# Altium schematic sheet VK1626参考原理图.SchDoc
size A4
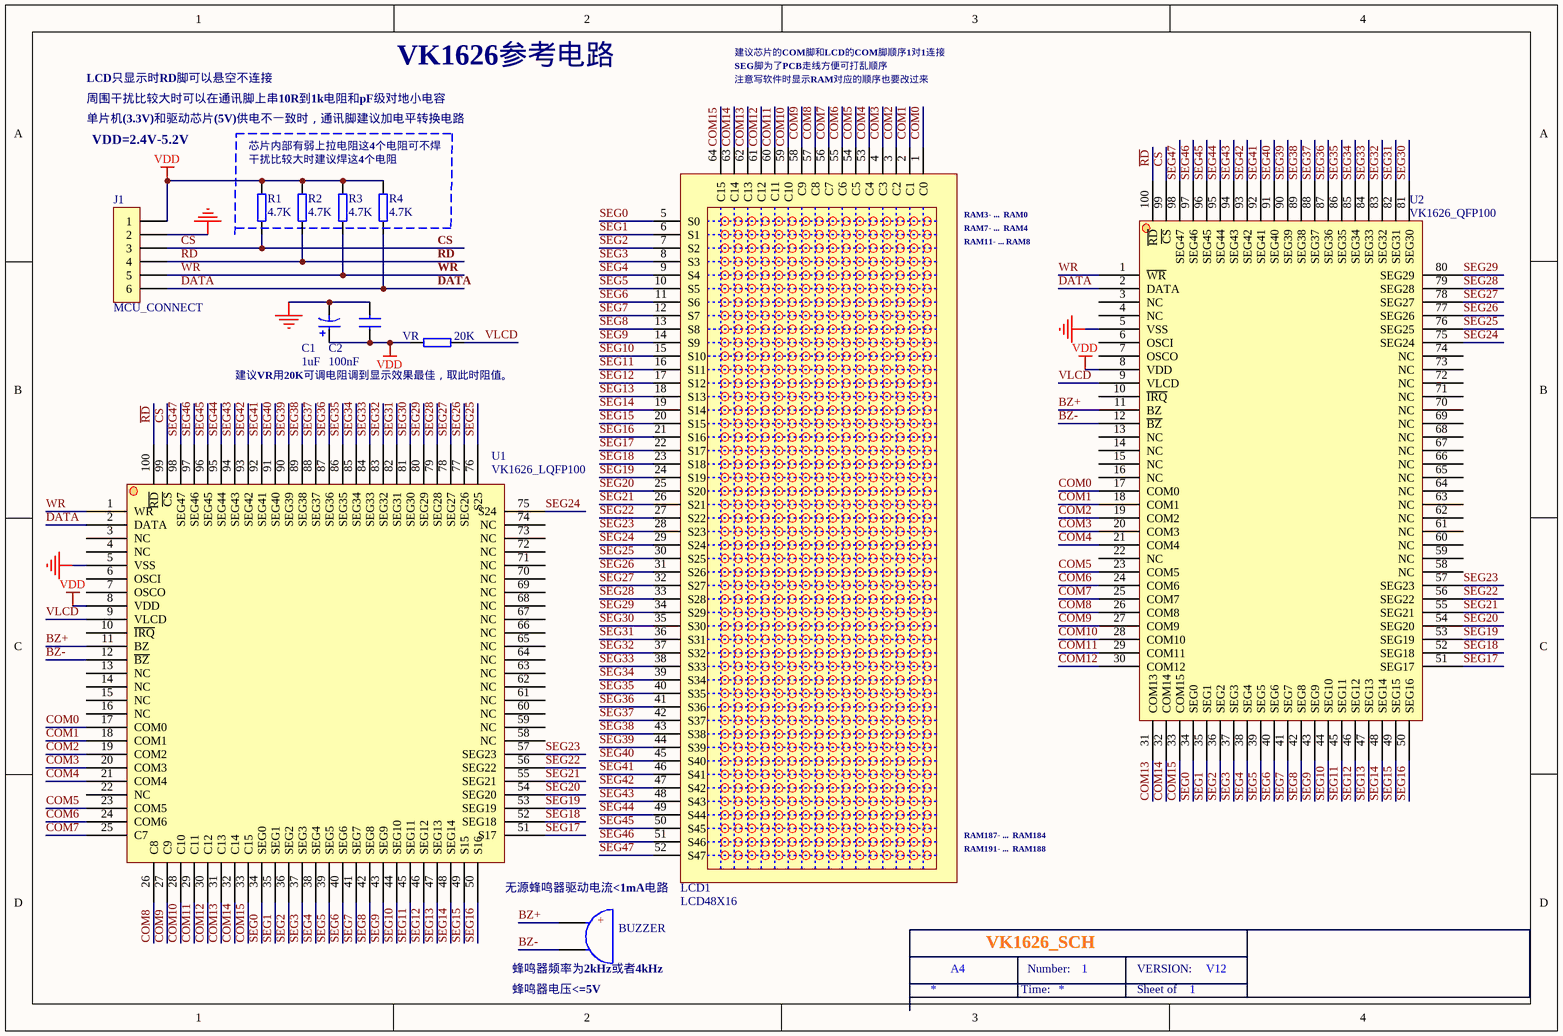
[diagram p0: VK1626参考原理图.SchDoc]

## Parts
B1  BUZZER  [BUZZER-12]
C1  1uF  [1206-C]
C2  100nF  [0603-C]
J1  MCU_CONNECT
LCD1  LCD48X16
R1  4.7K  [0603-R]
R2  4.7K  [0603-R]
R3  4.7K  [0603-R]
R4  4.7K  [0603-R]
U1  VK1626_LQFP100
U2  VK1626_QFP100
VR  20K  [0603-R]

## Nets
GND: C1.2 C2.2 J1.2 U1.5(VSS) U2.5(VSS)
VDD: C1.1 C2.1 J1.1 R1.1 R2.1 R3.1 R4.1 U1.8(VDD) U2.8(VDD) VR.1
~{CS}: U1.99(~{CS}) U2.99(~{CS})
~{RD}: U1.100(~{RD}) U2.100(~{RD})
BZ+: B1.1 U1.11(BZ) U2.11(BZ)
BZ-: B1.2 U1.12(~{BZ}) U2.12(~{BZ})
COM0: LCD1.1(C0) U1.17(COM0) U2.17(COM0)
COM1: LCD1.2(C1) U1.18(COM1) U2.18(COM1)
COM2: LCD1.3(C2) U1.19(COM2) U2.19(COM2)
COM3: LCD1.4(C3) U1.20(COM3) U2.20(COM3)
COM4: LCD1.53(C4) U1.21(COM4) U2.21(COM4)
COM5: LCD1.54(C5) U1.23(COM5) U2.23(COM5)
COM6: LCD1.55(C6) U1.24(COM6) U2.24(COM6)
COM7: LCD1.56(C7) U1.25(C7) U2.25(COM7)
COM8: LCD1.57(C8) U1.26(C8) U2.26(COM8)
COM9: LCD1.58(C9) U1.27(C9) U2.27(COM9)
COM10: LCD1.59(C10) U1.28(C10) U2.28(COM10)
COM11: LCD1.60(C11) U1.29(C11) U2.29(COM11)
COM12: LCD1.61(C12) U1.30(C12) U2.30(COM12)
COM13: LCD1.62(C13) U1.31(C13) U2.31(COM13)
COM14: LCD1.63(C14) U1.32(C14) U2.32(COM14)
COM15: LCD1.64(C15) U1.33(C15) U2.33(COM15)
CS: J1.3 R1.2
DATA: J1.6 R4.2 U1.2(DATA) U2.2(DATA)
RD: J1.4 R2.2
SEG0: LCD1.5(S0) U1.34(SEG0) U2.34(SEG0)
SEG1: LCD1.6(S1) U1.35(SEG1) U2.35(SEG1)
SEG2: LCD1.7(S2) U1.36(SEG2) U2.36(SEG2)
SEG3: LCD1.8(S3) U1.37(SEG3) U2.37(SEG3)
SEG4: LCD1.9(S4) U1.38(SEG4) U2.38(SEG4)
SEG5: LCD1.10(S5) U1.39(SEG5) U2.39(SEG5)
SEG6: LCD1.11(S6) U1.40(SEG6) U2.40(SEG6)
SEG7: LCD1.12(S7) U1.41(SEG7) U2.41(SEG7)
SEG8: LCD1.13(S8) U1.42(SEG8) U2.42(SEG8)
SEG9: LCD1.14(S9) U1.43(SEG9) U2.43(SEG9)
SEG10: LCD1.15(S10) U1.44(SEG10) U2.44(SEG10)
SEG11: LCD1.16(S11) U1.45(SEG11) U2.45(SEG11)
SEG12: LCD1.17(S12) U1.46(SEG12) U2.46(SEG12)
SEG13: LCD1.18(S13) U1.47(SEG13) U2.47(SEG13)
SEG14: LCD1.19(S14) U1.48(SEG14) U2.48(SEG14)
SEG15: LCD1.20(S15) U1.49(S15) U2.49(SEG15)
SEG16: LCD1.21(S16) U1.50(S16) U2.50(SEG16)
SEG17: LCD1.22(S17) U1.51(S17) U2.51(SEG17)
SEG18: LCD1.23(S18) U1.52(SEG18) U2.52(SEG18)
SEG19: LCD1.24(S19) U1.53(SEG19) U2.53(SEG19)
SEG20: LCD1.25(S20) U1.54(SEG20) U2.54(SEG20)
SEG21: LCD1.26(S21) U1.55(SEG21) U2.55(SEG21)
SEG22: LCD1.27(S22) U1.56(SEG22) U2.56(SEG22)
SEG23: LCD1.28(S23) U1.57(SEG23) U2.57(SEG23)
SEG24: LCD1.29(S24) U1.75(S24) U2.75(SEG24)
SEG25: LCD1.30(S25) U1.76(S25) U2.76(SEG25)
SEG26: LCD1.31(S26) U1.77(SEG26) U2.77(SEG26)
SEG27: LCD1.32(S27) U1.78(SEG27) U2.78(SEG27)
SEG28: LCD1.33(S28) U1.79(SEG28) U2.79(SEG28)
SEG29: LCD1.34(S29) U1.80(SEG29) U2.80(SEG29)
SEG30: LCD1.35(S30) U1.81(SEG30) U2.81(SEG30)
SEG31: LCD1.36(S31) U1.82(SEG31) U2.82(SEG31)
SEG32: LCD1.37(S32) U1.83(SEG32) U2.83(SEG32)
SEG33: LCD1.38(S33) U1.84(SEG33) U2.84(SEG33)
SEG34: LCD1.39(S34) U1.85(SEG34) U2.85(SEG34)
SEG35: LCD1.40(S35) U1.86(SEG35) U2.86(SEG35)
SEG36: LCD1.41(S36) U1.87(SEG36) U2.87(SEG36)
SEG37: LCD1.42(S37) U1.88(SEG37) U2.88(SEG37)
SEG38: LCD1.43(S38) U1.89(SEG38) U2.89(SEG38)
SEG39: LCD1.44(S39) U1.90(SEG39) U2.90(SEG39)
SEG40: LCD1.45(S40) U1.91(SEG40) U2.91(SEG40)
SEG41: LCD1.46(S41) U1.92(SEG41) U2.92(SEG41)
SEG42: LCD1.47(S42) U1.93(SEG42) U2.93(SEG42)
SEG43: LCD1.48(S43) U1.94(SEG43) U2.94(SEG43)
SEG44: LCD1.49(S44) U1.95(SEG44) U2.95(SEG44)
SEG45: LCD1.50(S45) U1.96(SEG45) U2.96(SEG45)
SEG46: LCD1.51(S46) U1.97(SEG46) U2.97(SEG46)
SEG47: LCD1.52(S47) U1.98(SEG47) U2.98(SEG47)
VLCD: U1.9(VLCD) U2.9(VLCD) VR.2
WR: J1.5 R3.2 U1.1(WR) U2.1(~{WR})

Not connected (* = marked no-connect by the designer): U1 3(NC) 4(NC) 6(OSCI) 7(OSCO) 10(~{IRQ}) 13(NC) 14(NC) 15(NC) 16(NC) 22(NC) 58(NC) 59(NC) 60(NC) 61(NC) 62(NC) 63(NC) 64(NC) 65(NC) 66(NC) 67(NC) 68(NC) 69(NC) 70(NC) 71(NC) 72(NC) 73(NC) 74(NC); U2 3(NC) 4(NC) 6(OSCI) 7(OSCO) 10(~{IRQ}) 13(NC) 14(NC) 15(NC) 16(NC) 22(NC) 58(NC) 59(NC) 60(NC) 61(NC) 62(NC) 63(NC) 64(NC) 65(NC) 66(NC) 67(NC) 68(NC) 69(NC) 70(NC) 71(NC) 72(NC) 73(NC) 74(NC)

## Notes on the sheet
- 周围干扰比较大时可以在通讯脚上串10R到1k电阻和pF级对地小电容
- LCD只显示时RD脚可以悬空不连接
- VK1626参考电路
- 建议芯片的COM脚和LCD的COM脚顺序1对1连接
- SEG脚为了PCB走线方便可打乱顺序
- 注意写软件时显示RAM对应的顺序也要改过来
- 单片机(3.3V)和驱动芯片(5V)供电不一致时，通讯脚建议加电平转换电路
- VDD=2.4V-5.2V
- 芯片内部有弱上拉电阻这4个电阻可不焊
- 干扰比较大时建议焊这4个电阻
- CS
- (near LCD1) RAM3- ...  RAM0
- (near LCD1) RAM7- ...  RAM4
- (near LCD1) RAM11- ... RAM8
- WR
- DATA
- RD
- 建议VR用20K可调电阻调到显示效果最佳，取此时阻值。
- (near LCD1) RAM191- ...  RAM188
- (near LCD1) RAM187- ...  RAM184
- 无源蜂鸣器驱动电流<1mA电路
- (near B1) 蜂鸣器频率为2kHz或者4kHz
- A4
- VK1626_SCH
- Number:
- 1
- VERSION:
- V12
- (near B1) 蜂鸣器电压<=5V
- Time:
- Sheet of

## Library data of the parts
C1 = ECAP: Bi-Polar Capacitor
C2 = CAP: Capacitor
J1 = CON6: Connector
R1-R4 VR = RES: Resistor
